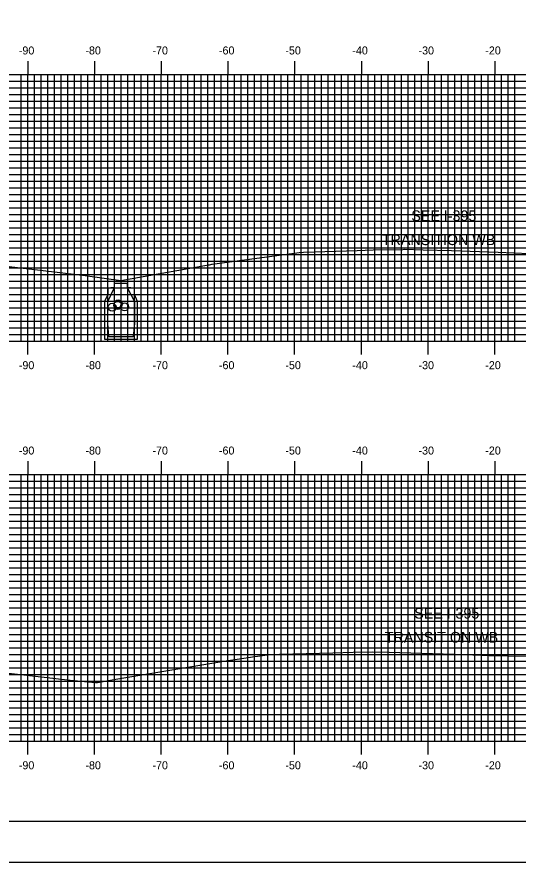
# Model space of a CAD drawing. Extents: x 853721 to 854064, y 364661 to 364881.
# Drawn here: x 853795.2 to 853870.3, y 364661.3 to 364788 of the extents above; entities that cross this region are included whole.
import ezdxf

# ---------------------------------------------------------------- set-up
doc = ezdxf.new("R2010")
doc.units = 0
for name, color, linetype in [('ANNOTATION', 7, 'Continuous'), ('BORDER', 7, 'Continuous'), ('H_V ANNOTATION', 7, 'Continuous'), ('M_Roadway_Centerline', 7, 'Continuous'), ('MAJOR', 7, 'Continuous'), ('MINOR', 7, 'Continuous'), ('PLOT BOUNDARY', 7, 'Continuous'), ('S_Drainage_CB', 7, 'Continuous'), ('S_Drainage_Invert', 7, 'Continuous'), ('S_Roadway_Centerline', 7, 'Continuous')]:
    doc.layers.add(name, color=color, linetype=linetype)

msp = doc.modelspace()

# ---------------------------------------------------------------- linework, layer by layer
at = {"layer": 'BORDER'}
msp.add_lwpolyline([(853737.21, 364667.37), (854057.21, 364667.37), (854057.21, 364877.37), (853737.21, 364877.37)], close=True, dxfattribs=at)
at = {"layer": 'MAJOR'}
for p, q in [((853796.81, 364781.37), (853796.81, 364779.37)), ((853806.81, 364781.37), (853806.81, 364779.37)), ((853816.81, 364781.37), (853816.81, 364779.37)), ((853826.81, 364781.37), (853826.81, 364779.37)), ((853836.81, 364781.37), (853836.81, 364779.37)), ((853846.81, 364781.37), (853846.81, 364779.37)), ((853856.81, 364781.37), (853856.81, 364779.37)), ((853866.81, 364781.37), (853866.81, 364779.37)), ((853746.81, 364779.37), (854026.81, 364779.37)), ((853746.81, 364779.37), (854026.81, 364779.37)), ((853796.81, 364739.37), (853796.81, 364779.37)), ((853806.81, 364739.37), (853806.81, 364779.37)), ((853816.81, 364739.37), (853816.81, 364779.37)), ((853826.81, 364739.37), (853826.81, 364779.37)), ((853836.81, 364739.37), (853836.81, 364779.37)), ((853846.81, 364739.37), (853846.81, 364779.37)), ((853856.81, 364739.37), (853856.81, 364779.37)), ((853866.81, 364739.37), (853866.81, 364779.37)), ((853746.81, 364774.37), (854026.81, 364774.37)), ((853746.81, 364769.37), (854026.81, 364769.37)), ((853746.81, 364764.37), (854026.81, 364764.37)), ((853746.81, 364759.37), (854026.81, 364759.37)), ((853746.81, 364754.37), (854026.81, 364754.37)), ((853746.81, 364749.37), (854026.81, 364749.37)), ((853746.81, 364744.37), (854026.81, 364744.37)), ((853746.81, 364739.37), (854026.81, 364739.37)), ((853746.81, 364739.37), (854026.81, 364739.37)), ((853796.81, 364737.37), (853796.81, 364739.37)), ((853806.81, 364737.37), (853806.81, 364739.37)), ((853816.81, 364737.37), (853816.81, 364739.37)), ((853826.81, 364737.37), (853826.81, 364739.37)), ((853836.81, 364737.37), (853836.81, 364739.37)), ((853846.81, 364737.37), (853846.81, 364739.37)), ((853856.81, 364737.37), (853856.81, 364739.37)), ((853866.81, 364737.37), (853866.81, 364739.37)), ((853796.81, 364721.37), (853796.81, 364719.37)), ((853806.81, 364721.37), (853806.81, 364719.37)), ((853816.81, 364721.37), (853816.81, 364719.37)), ((853826.81, 364721.37), (853826.81, 364719.37)), ((853836.81, 364721.37), (853836.81, 364719.37)), ((853846.81, 364721.37), (853846.81, 364719.37)), ((853856.81, 364721.37), (853856.81, 364719.37)), ((853866.81, 364721.37), (853866.81, 364719.37)), ((853746.81, 364719.37), (854026.81, 364719.37)), ((853746.81, 364719.37), (854026.81, 364719.37)), ((853796.81, 364679.37), (853796.81, 364719.37)), ((853806.81, 364679.37), (853806.81, 364719.37)), ((853816.81, 364679.37), (853816.81, 364719.37)), ((853826.81, 364679.37), (853826.81, 364719.37)), ((853836.81, 364679.37), (853836.81, 364719.37)), ((853846.81, 364679.37), (853846.81, 364719.37)), ((853856.81, 364679.37), (853856.81, 364719.37)), ((853866.81, 364679.37), (853866.81, 364719.37)), ((853746.81, 364714.37), (854026.81, 364714.37)), ((853746.81, 364709.37), (854026.81, 364709.37)), ((853746.81, 364704.37), (854026.81, 364704.37)), ((853746.81, 364699.37), (854026.81, 364699.37)), ((853746.81, 364694.37), (854026.81, 364694.37)), ((853746.81, 364689.37), (854026.81, 364689.37)), ((853746.81, 364684.37), (854026.81, 364684.37)), ((853746.81, 364679.37), (854026.81, 364679.37)), ((853746.81, 364679.37), (854026.81, 364679.37)), ((853796.81, 364677.37), (853796.81, 364679.37)), ((853806.81, 364677.37), (853806.81, 364679.37)), ((853816.81, 364677.37), (853816.81, 364679.37)), ((853826.81, 364677.37), (853826.81, 364679.37)), ((853836.81, 364677.37), (853836.81, 364679.37)), ((853846.81, 364677.37), (853846.81, 364679.37)), ((853856.81, 364677.37), (853856.81, 364679.37)), ((853866.81, 364677.37), (853866.81, 364679.37))]:
    msp.add_line(p, q, dxfattribs=at)
at = {"layer": 'MINOR'}
for p, q in [((853746.81, 364778.37), (854026.81, 364778.37)), ((853795.81, 364739.37), (853795.81, 364779.37)), ((853797.81, 364739.37), (853797.81, 364779.37)), ((853798.81, 364739.37), (853798.81, 364779.37)), ((853799.81, 364739.37), (853799.81, 364779.37)), ((853800.81, 364739.37), (853800.81, 364779.37)), ((853801.81, 364739.37), (853801.81, 364779.37)), ((853802.81, 364739.37), (853802.81, 364779.37)), ((853803.81, 364739.37), (853803.81, 364779.37)), ((853804.81, 364739.37), (853804.81, 364779.37)), ((853805.81, 364739.37), (853805.81, 364779.37)), ((853807.81, 364739.37), (853807.81, 364779.37)), ((853808.81, 364739.37), (853808.81, 364779.37)), ((853809.81, 364739.37), (853809.81, 364779.37)), ((853810.81, 364739.37), (853810.81, 364779.37)), ((853811.81, 364739.37), (853811.81, 364779.37)), ((853812.81, 364739.37), (853812.81, 364779.37)), ((853813.81, 364739.37), (853813.81, 364779.37)), ((853814.81, 364739.37), (853814.81, 364779.37)), ((853815.81, 364739.37), (853815.81, 364779.37)), ((853817.81, 364739.37), (853817.81, 364779.37)), ((853818.81, 364739.37), (853818.81, 364779.37)), ((853819.81, 364739.37), (853819.81, 364779.37)), ((853820.81, 364739.37), (853820.81, 364779.37)), ((853821.81, 364739.37), (853821.81, 364779.37)), ((853822.81, 364739.37), (853822.81, 364779.37)), ((853823.81, 364739.37), (853823.81, 364779.37)), ((853824.81, 364739.37), (853824.81, 364779.37)), ((853825.81, 364739.37), (853825.81, 364779.37)), ((853827.81, 364739.37), (853827.81, 364779.37)), ((853828.81, 364739.37), (853828.81, 364779.37)), ((853829.81, 364739.37), (853829.81, 364779.37)), ((853830.81, 364739.37), (853830.81, 364779.37)), ((853831.81, 364739.37), (853831.81, 364779.37)), ((853832.81, 364739.37), (853832.81, 364779.37)), ((853833.81, 364739.37), (853833.81, 364779.37)), ((853834.81, 364739.37), (853834.81, 364779.37)), ((853835.81, 364739.37), (853835.81, 364779.37)), ((853837.81, 364739.37), (853837.81, 364779.37)), ((853838.81, 364739.37), (853838.81, 364779.37)), ((853839.81, 364739.37), (853839.81, 364779.37)), ((853840.81, 364739.37), (853840.81, 364779.37)), ((853841.81, 364739.37), (853841.81, 364779.37)), ((853842.81, 364739.37), (853842.81, 364779.37)), ((853843.81, 364739.37), (853843.81, 364779.37)), ((853844.81, 364739.37), (853844.81, 364779.37)), ((853845.81, 364739.37), (853845.81, 364779.37)), ((853847.81, 364739.37), (853847.81, 364779.37)), ((853848.81, 364739.37), (853848.81, 364779.37)), ((853849.81, 364739.37), (853849.81, 364779.37)), ((853850.81, 364739.37), (853850.81, 364779.37)), ((853851.81, 364739.37), (853851.81, 364779.37)), ((853852.81, 364739.37), (853852.81, 364779.37)), ((853853.81, 364739.37), (853853.81, 364779.37)), ((853854.81, 364739.37), (853854.81, 364779.37)), ((853855.81, 364739.37), (853855.81, 364779.37)), ((853857.81, 364739.37), (853857.81, 364779.37)), ((853858.81, 364739.37), (853858.81, 364779.37)), ((853859.81, 364739.37), (853859.81, 364779.37)), ((853860.81, 364739.37), (853860.81, 364779.37)), ((853861.81, 364739.37), (853861.81, 364779.37)), ((853862.81, 364739.37), (853862.81, 364779.37)), ((853863.81, 364739.37), (853863.81, 364779.37)), ((853864.81, 364739.37), (853864.81, 364779.37)), ((853865.81, 364739.37), (853865.81, 364779.37)), ((853867.81, 364739.37), (853867.81, 364779.37)), ((853868.81, 364739.37), (853868.81, 364779.37)), ((853869.81, 364739.37), (853869.81, 364779.37)), ((853746.81, 364777.37), (854026.81, 364777.37)), ((853746.81, 364776.37), (854026.81, 364776.37)), ((853746.81, 364775.37), (854026.81, 364775.37)), ((853746.81, 364773.37), (854026.81, 364773.37)), ((853746.81, 364772.37), (854026.81, 364772.37)), ((853746.81, 364771.37), (854026.81, 364771.37)), ((853746.81, 364770.37), (854026.81, 364770.37)), ((853746.81, 364768.37), (854026.81, 364768.37)), ((853746.81, 364767.37), (854026.81, 364767.37)), ((853746.81, 364766.37), (854026.81, 364766.37)), ((853746.81, 364765.37), (854026.81, 364765.37)), ((853746.81, 364763.37), (854026.81, 364763.37)), ((853746.81, 364762.37), (854026.81, 364762.37)), ((853746.81, 364761.37), (854026.81, 364761.37)), ((853746.81, 364760.37), (854026.81, 364760.37)), ((853746.81, 364758.37), (854026.81, 364758.37)), ((853746.81, 364757.37), (854026.81, 364757.37)), ((853746.81, 364756.37), (854026.81, 364756.37)), ((853746.81, 364755.37), (854026.81, 364755.37)), ((853746.81, 364753.37), (854026.81, 364753.37)), ((853746.81, 364752.37), (854026.81, 364752.37)), ((853746.81, 364751.37), (854026.81, 364751.37)), ((853746.81, 364750.37), (854026.81, 364750.37)), ((853746.81, 364748.37), (854026.81, 364748.37)), ((853746.81, 364747.37), (854026.81, 364747.37)), ((853746.81, 364746.37), (854026.81, 364746.37)), ((853746.81, 364745.37), (854026.81, 364745.37)), ((853746.81, 364743.37), (854026.81, 364743.37)), ((853746.81, 364742.37), (854026.81, 364742.37)), ((853746.81, 364741.37), (854026.81, 364741.37)), ((853746.81, 364740.37), (854026.81, 364740.37)), ((853795.81, 364679.37), (853795.81, 364719.37)), ((853797.81, 364679.37), (853797.81, 364719.37)), ((853798.81, 364679.37), (853798.81, 364719.37)), ((853799.81, 364679.37), (853799.81, 364719.37)), ((853800.81, 364679.37), (853800.81, 364719.37)), ((853801.81, 364679.37), (853801.81, 364719.37)), ((853802.81, 364679.37), (853802.81, 364719.37)), ((853803.81, 364679.37), (853803.81, 364719.37)), ((853804.81, 364679.37), (853804.81, 364719.37)), ((853805.81, 364679.37), (853805.81, 364719.37)), ((853807.81, 364679.37), (853807.81, 364719.37)), ((853808.81, 364679.37), (853808.81, 364719.37)), ((853809.81, 364679.37), (853809.81, 364719.37)), ((853810.81, 364679.37), (853810.81, 364719.37)), ((853811.81, 364679.37), (853811.81, 364719.37)), ((853812.81, 364679.37), (853812.81, 364719.37)), ((853813.81, 364679.37), (853813.81, 364719.37)), ((853814.81, 364679.37), (853814.81, 364719.37)), ((853815.81, 364679.37), (853815.81, 364719.37)), ((853817.81, 364679.37), (853817.81, 364719.37)), ((853818.81, 364679.37), (853818.81, 364719.37)), ((853819.81, 364679.37), (853819.81, 364719.37)), ((853820.81, 364679.37), (853820.81, 364719.37)), ((853821.81, 364679.37), (853821.81, 364719.37)), ((853822.81, 364679.37), (853822.81, 364719.37)), ((853823.81, 364679.37), (853823.81, 364719.37)), ((853824.81, 364679.37), (853824.81, 364719.37)), ((853825.81, 364679.37), (853825.81, 364719.37)), ((853827.81, 364679.37), (853827.81, 364719.37)), ((853828.81, 364679.37), (853828.81, 364719.37)), ((853829.81, 364679.37), (853829.81, 364719.37)), ((853830.81, 364679.37), (853830.81, 364719.37)), ((853831.81, 364679.37), (853831.81, 364719.37)), ((853832.81, 364679.37), (853832.81, 364719.37)), ((853833.81, 364679.37), (853833.81, 364719.37)), ((853834.81, 364679.37), (853834.81, 364719.37)), ((853835.81, 364679.37), (853835.81, 364719.37)), ((853837.81, 364679.37), (853837.81, 364719.37)), ((853838.81, 364679.37), (853838.81, 364719.37)), ((853839.81, 364679.37), (853839.81, 364719.37)), ((853840.81, 364679.37), (853840.81, 364719.37)), ((853841.81, 364679.37), (853841.81, 364719.37)), ((853842.81, 364679.37), (853842.81, 364719.37)), ((853843.81, 364679.37), (853843.81, 364719.37)), ((853844.81, 364679.37), (853844.81, 364719.37)), ((853845.81, 364679.37), (853845.81, 364719.37)), ((853847.81, 364679.37), (853847.81, 364719.37)), ((853848.81, 364679.37), (853848.81, 364719.37)), ((853849.81, 364679.37), (853849.81, 364719.37)), ((853850.81, 364679.37), (853850.81, 364719.37)), ((853851.81, 364679.37), (853851.81, 364719.37)), ((853852.81, 364679.37), (853852.81, 364719.37)), ((853853.81, 364679.37), (853853.81, 364719.37)), ((853854.81, 364679.37), (853854.81, 364719.37)), ((853855.81, 364679.37), (853855.81, 364719.37)), ((853857.81, 364679.37), (853857.81, 364719.37)), ((853858.81, 364679.37), (853858.81, 364719.37)), ((853859.81, 364679.37), (853859.81, 364719.37)), ((853860.81, 364679.37), (853860.81, 364719.37)), ((853861.81, 364679.37), (853861.81, 364719.37)), ((853862.81, 364679.37), (853862.81, 364719.37)), ((853863.81, 364679.37), (853863.81, 364719.37)), ((853864.81, 364679.37), (853864.81, 364719.37)), ((853865.81, 364679.37), (853865.81, 364719.37)), ((853867.81, 364679.37), (853867.81, 364719.37)), ((853868.81, 364679.37), (853868.81, 364719.37)), ((853869.81, 364679.37), (853869.81, 364719.37)), ((853746.81, 364718.37), (854026.81, 364718.37)), ((853746.81, 364717.37), (854026.81, 364717.37)), ((853746.81, 364716.37), (854026.81, 364716.37)), ((853746.81, 364715.37), (854026.81, 364715.37)), ((853746.81, 364713.37), (854026.81, 364713.37)), ((853746.81, 364712.37), (854026.81, 364712.37)), ((853746.81, 364711.37), (854026.81, 364711.37)), ((853746.81, 364710.37), (854026.81, 364710.37)), ((853746.81, 364708.37), (854026.81, 364708.37)), ((853746.81, 364707.37), (854026.81, 364707.37)), ((853746.81, 364706.37), (854026.81, 364706.37)), ((853746.81, 364705.37), (854026.81, 364705.37)), ((853746.81, 364703.37), (854026.81, 364703.37)), ((853746.81, 364702.37), (854026.81, 364702.37)), ((853746.81, 364701.37), (854026.81, 364701.37)), ((853746.81, 364700.37), (854026.81, 364700.37)), ((853746.81, 364698.37), (854026.81, 364698.37)), ((853746.81, 364697.37), (854026.81, 364697.37)), ((853746.81, 364696.37), (854026.81, 364696.37)), ((853746.81, 364695.37), (854026.81, 364695.37)), ((853746.81, 364693.37), (854026.81, 364693.37)), ((853746.81, 364692.37), (854026.81, 364692.37)), ((853746.81, 364691.37), (854026.81, 364691.37)), ((853746.81, 364690.37), (854026.81, 364690.37)), ((853746.81, 364688.37), (854026.81, 364688.37)), ((853746.81, 364687.37), (854026.81, 364687.37)), ((853746.81, 364686.37), (854026.81, 364686.37)), ((853746.81, 364685.37), (854026.81, 364685.37)), ((853746.81, 364683.37), (854026.81, 364683.37)), ((853746.81, 364682.37), (854026.81, 364682.37)), ((853746.81, 364681.37), (854026.81, 364681.37)), ((853746.81, 364680.37), (854026.81, 364680.37))]:
    msp.add_line(p, q, dxfattribs=at)
at = {"layer": 'PLOT BOUNDARY'}
msp.add_lwpolyline([(853721.02, 364661.25), (854061.02, 364661.25), (854061.02, 364881.25), (853721.02, 364881.25)], close=True, dxfattribs=at)
at = {"layer": 'S_Drainage_CB'}
for p, q in [((853809.76, 364747.34), (853808.78, 364747.34)), ((853808.78, 364747.34), (853808.78, 364746.35)), ((853808.78, 364745.33), (853809.76, 364747.34)), ((853812.78, 364747.34), (853811.76, 364747.34)), ((853811.76, 364747.34), (853812.78, 364745.33)), ((853812.78, 364746.35), (853812.78, 364747.34)), ((853808.78, 364746.35), (853808.29, 364745.33)), ((853808.29, 364745.33), (853808.29, 364739.69)), ((853808.78, 364742.02), (853808.78, 364745.33)), ((853813.27, 364745.33), (853812.78, 364746.35)), ((853812.78, 364745.33), (853812.78, 364742.02)), ((853813.27, 364739.69), (853813.27, 364745.33)), ((853808.94, 364740.02), (853808.78, 364742.02)), ((853812.78, 364742.02), (853812.62, 364740.02)), ((853808.29, 364739.69), (853813.27, 364739.69)), ((853812.62, 364740.02), (853808.94, 364740.02))]:
    msp.add_line(p, q, dxfattribs=at)
msp.add_lwpolyline([(853812.26, 364747.38), (853811.76, 364747.38), (853811.76, 364748), (853809.76, 364748), (853809.76, 364747.38), (853809.27, 364747.38)], dxfattribs=at)
at = {"layer": 'S_Drainage_Invert'}
for centre in [(853810.29, 364744.73), (853810.33, 364744.95), (853809.45, 364744.47), (853811.32, 364744.52)]:
    msp.add_circle(centre, 0.6, dxfattribs=at)
at = {"layer": 'S_Roadway_Centerline'}
for points in [[(853784.21, 364751.73), (853799.5, 364749.93), (853805.41, 364749.21), (853810.73, 364748.49), (853823.35, 364750.72), (853823.91, 364750.81), (853824.03, 364750.84), (853824.23, 364750.88), (853824.38, 364750.91), (853824.44, 364750.92), (853837.49, 364752.69), (853838.14, 364752.72), (853846.19, 364752.99), (853848.58, 364753.05), (853853.02, 364753.13), (853853.21, 364753.16), (853856.09, 364753.07), (853860.3, 364752.98), (853867.34, 364752.73), (853872.03, 364752.52)], [(853785.01, 364690.52), (853796.19, 364689.32), (853803.13, 364688.55), (853806.93, 364688.16), (853807.24, 364688.18), (853810.29, 364688.74), (853825.88, 364691.32), (853830.84, 364692.06), (853832.74, 364692.34), (853834.53, 364692.41), (853842.51, 364692.63), (853845.6, 364692.71), (853848.44, 364692.8), (853850.98, 364692.73), (853862.31, 364692.36), (853865.98, 364692.25), (853868.81, 364692.17), (853877.39, 364692.06)]]:
    msp.add_lwpolyline(points, dxfattribs=at)

# ---------------------------------------------------------------- texts
at = {"layer": 'ANNOTATION'}
for s, p in [('SEE I-395 ', (853854.3, 364757.38)), ('TRANSITION WB', (853849.89, 364753.78)), ('SEE I-395 ', (853854.74, 364697.77)), ('TRANSITION WB', (853850.33, 364694.17))]:
    msp.add_text(s, height=1.6, dxfattribs=at).set_placement(p)
at = {"layer": 'H_V ANNOTATION'}
for s, p in [('-90', (853795.46, 364782.37)), ('-80', (853805.44, 364782.37)), ('-70', (853815.49, 364782.37)), ('-60', (853825.46, 364782.37)), ('-50', (853835.42, 364782.37)), ('-40', (853845.46, 364782.37)), ('-30', (853855.38, 364782.37)), ('-20', (853865.39, 364782.37)), ('-90', (853795.46, 364735.17)), ('-80', (853805.44, 364735.17)), ('-70', (853815.49, 364735.17)), ('-60', (853825.46, 364735.17)), ('-50', (853835.42, 364735.17)), ('-40', (853845.46, 364735.17)), ('-30', (853855.38, 364735.17)), ('-20', (853865.39, 364735.17)), ('-90', (853795.46, 364722.37)), ('-80', (853805.44, 364722.37)), ('-70', (853815.49, 364722.37)), ('-60', (853825.46, 364722.37)), ('-50', (853835.42, 364722.37)), ('-40', (853845.46, 364722.37)), ('-30', (853855.38, 364722.37)), ('-20', (853865.39, 364722.37)), ('-90', (853795.46, 364675.17)), ('-80', (853805.44, 364675.17)), ('-70', (853815.49, 364675.17)), ('-60', (853825.46, 364675.17)), ('-50', (853835.42, 364675.17)), ('-40', (853845.46, 364675.17)), ('-30', (853855.38, 364675.17)), ('-20', (853865.39, 364675.17))]:
    msp.add_text(s, height=1.2, dxfattribs=at).set_placement(p)
at = {"layer": 'M_Roadway_Centerline'}
for s, p in [('C', (853853.2, 364753.16)), ('L', (853853.21, 364753.16)), ('C', (853848.43, 364692.8)), ('L', (853848.44, 364692.79))]:
    msp.add_text(s, height=0.0146, dxfattribs=at).set_placement(p)

doc.saveas('drawing.dxf')
